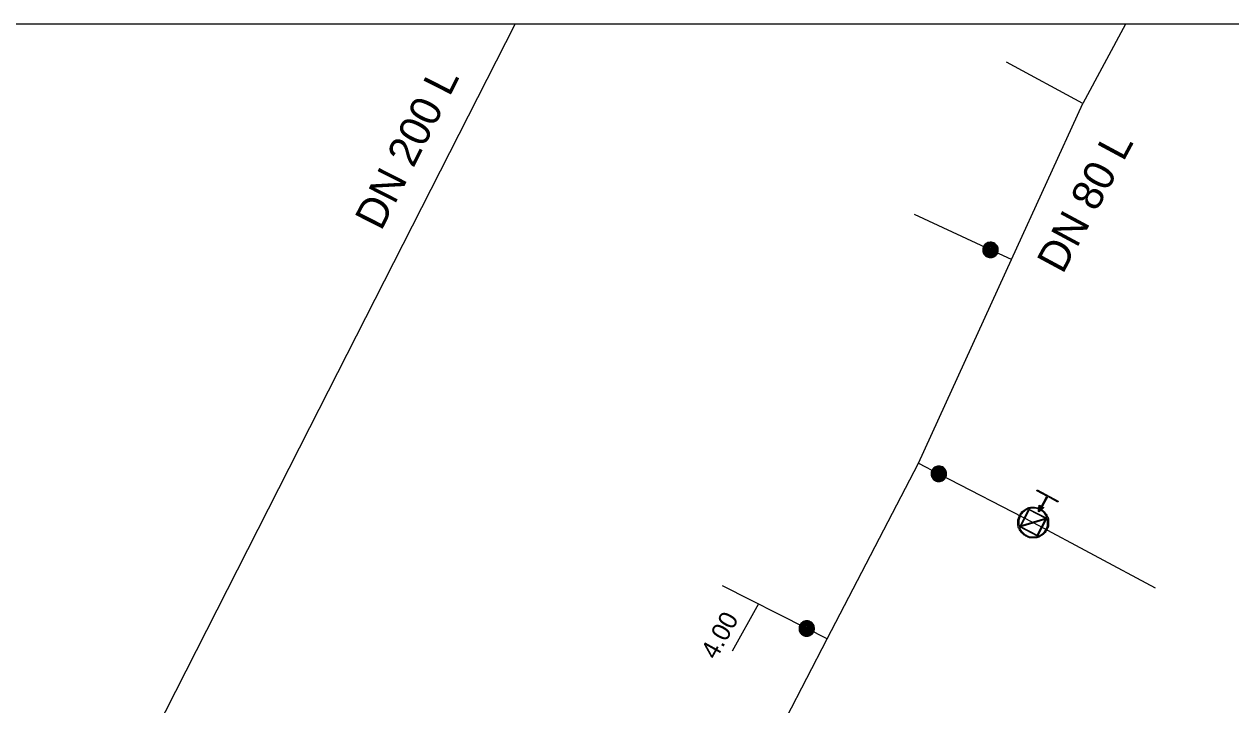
# Model space of a CAD drawing. Extents: x -820257 to -819974, y -1070894 to -1070484.
# Drawn here: x -820109.2 to -820030.6, y -1070528.7 to -1070484.4 of the extents above; entities that cross this region are included whole.
import ezdxf

# ---------------------------------------------------------------- set-up
doc = ezdxf.new("R2010")
doc.units = 0
for name, color, linetype in [('Default', 7, 'Continuous'), ('Hydrant', 7, 'Continuous'), ('Oměrka vodovodu', 7, 'Continuous'), ('Oměrka-text', 7, 'Continuous'), ('Přípojka vodovodu', 7, 'Continuous'), ('Přípojkový uzávěr', 7, 'Continuous'), ('Roz-řad', 7, 'Continuous'), ('Roz-řad-popis základní', 7, 'Continuous'), ('Šachta vodovodní', 7, 'Continuous')]:
    doc.layers.add(name, color=color, linetype=linetype)

msp = doc.modelspace()

# ---------------------------------------------------------------- linework, layer by layer
at = {"layer": 'Default'}
msp.add_lwpolyline([(-819975.603, -1070484.403), (-820256.81, -1070484.403), (-820256.81, -1070893.932)], dxfattribs=at)
at = {"layer": 'Hydrant'}
for points in [[(-820043.051, -1070515.965), (-820042.608, -1070515.138), (-820043.27, -1070514.785), (-820043.24, -1070514.73), (-820041.862, -1070515.466), (-820041.892, -1070515.522), (-820042.553, -1070515.168), (-820042.995, -1070515.995)], [(-820044.402, -1070517.105), (-820042.605, -1070516.56)], [(-820042.587, -1070516.618), (-820044.385, -1070517.165)]]:
    msp.add_lwpolyline(points, dxfattribs=at)
for points in [[(-820042.995, -1070515.995), (-820042.791, -1070516.113), (-820042.65, -1070516.326), (-820042.5, -1070516.552), (-820042.495, -1070516.827), (-820042.489, -1070517.102), (-820042.613, -1070517.333), (-820042.735, -1070517.562), (-820042.964, -1070517.71), (-820043.192, -1070517.858), (-820043.465, -1070517.862), (-820043.737, -1070517.866), (-820043.966, -1070517.744), (-820044.195, -1070517.621), (-820044.343, -1070517.392), (-820044.491, -1070517.164), (-820044.495, -1070516.892), (-820044.499, -1070516.619), (-820044.376, -1070516.39), (-820044.253, -1070516.159), (-820044.021, -1070516.011), (-820043.789, -1070515.863), (-820043.518, -1070515.861), (-820043.264, -1070515.86), (-820043.051, -1070515.965)], [(-820042.605, -1070516.56), (-820042.641, -1070516.454), (-820042.703, -1070516.359), (-820042.844, -1070516.146), (-820043.052, -1070516.035), (-820043.261, -1070515.924), (-820043.516, -1070515.924), (-820043.771, -1070515.925), (-820043.988, -1070516.064), (-820044.205, -1070516.203), (-820044.321, -1070516.42), (-820044.436, -1070516.635), (-820044.431, -1070516.89), (-820044.431, -1070517.001), (-820044.402, -1070517.105)], [(-820044.385, -1070517.165), (-820044.351, -1070517.266), (-820044.289, -1070517.358), (-820044.152, -1070517.573), (-820043.937, -1070517.688), (-820043.721, -1070517.804), (-820043.466, -1070517.8), (-820043.21, -1070517.796), (-820042.996, -1070517.657), (-820042.783, -1070517.519), (-820042.668, -1070517.304), (-820042.552, -1070517.087), (-820042.558, -1070516.829), (-820042.561, -1070516.719), (-820042.587, -1070516.618)]]:
    msp.add_open_spline(points, degree=3, dxfattribs=at)
at = {"layer": 'Oměrka vodovodu'}
msp.add_line((-820061.389, -1070522.16), (-820063.095, -1070525.238), dxfattribs=at)
at = {"layer": 'Přípojka vodovodu'}
for p, q in [((-820040.271, -1070489.57), (-820045.234, -1070486.875)), ((-820043.495, -1070516.863), (-820035.556, -1070521.108))]:
    msp.add_line(p, q, dxfattribs=at)
for points in [[(-820044.916, -1070499.74), (-820046.276, -1070499.108), (-820051.225, -1070496.806)], [(-820050.972, -1070512.997), (-820049.64, -1070513.686), (-820043.495, -1070516.863)], [(-820056.904, -1070524.441), (-820058.241, -1070523.761), (-820063.715, -1070520.977)]]:
    msp.add_lwpolyline(points, dxfattribs=at)
at = {"layer": 'Přípojkový uzávěr'}
for points in [[(-820046.065, -1070498.654), (-820045.951, -1070498.707), (-820045.87, -1070498.816), (-820045.789, -1070498.925), (-820045.778, -1070499.062), (-820045.767, -1070499.2), (-820045.823, -1070499.319), (-820045.877, -1070499.437), (-820045.987, -1070499.517), (-820046.097, -1070499.597), (-820046.233, -1070499.606), (-820046.369, -1070499.616), (-820046.487, -1070499.561), (-820046.604, -1070499.506), (-820046.685, -1070499.396), (-820046.765, -1070499.286), (-820046.775, -1070499.15), (-820046.784, -1070499.015), (-820046.729, -1070498.897), (-820046.674, -1070498.778), (-820046.563, -1070498.698), (-820046.451, -1070498.617), (-820046.315, -1070498.609), (-820046.18, -1070498.601), (-820046.065, -1070498.654)], [(-820046.085, -1070498.696), (-820046.189, -1070498.648), (-820046.312, -1070498.655), (-820046.435, -1070498.663), (-820046.536, -1070498.736), (-820046.637, -1070498.809), (-820046.687, -1070498.917), (-820046.736, -1070499.024), (-820046.728, -1070499.146), (-820046.719, -1070499.269), (-820046.646, -1070499.369), (-820046.574, -1070499.469), (-820046.467, -1070499.518), (-820046.36, -1070499.568), (-820046.237, -1070499.559), (-820046.114, -1070499.551), (-820046.014, -1070499.478), (-820045.915, -1070499.406), (-820045.865, -1070499.299), (-820045.815, -1070499.191), (-820045.825, -1070499.067), (-820045.835, -1070498.942), (-820045.908, -1070498.843), (-820045.982, -1070498.745), (-820046.085, -1070498.696)], [(-820046.1, -1070498.727), (-820046.003, -1070498.772), (-820045.936, -1070498.863), (-820045.868, -1070498.954), (-820045.859, -1070499.07), (-820045.85, -1070499.185), (-820045.896, -1070499.285), (-820045.942, -1070499.383), (-820046.034, -1070499.45), (-820046.126, -1070499.518), (-820046.24, -1070499.525), (-820046.354, -1070499.533), (-820046.453, -1070499.487), (-820046.551, -1070499.441), (-820046.619, -1070499.349), (-820046.686, -1070499.257), (-820046.694, -1070499.143), (-820046.702, -1070499.03), (-820046.656, -1070498.931), (-820046.61, -1070498.832), (-820046.516, -1070498.764), (-820046.423, -1070498.696), (-820046.309, -1070498.69), (-820046.195, -1070498.683), (-820046.1, -1070498.727)], [(-820046.119, -1070498.767), (-820046.26, -1070498.701), (-820046.405, -1070498.755), (-820046.55, -1070498.809), (-820046.616, -1070498.95), (-820046.682, -1070499.091), (-820046.628, -1070499.236), (-820046.575, -1070499.382), (-820046.435, -1070499.447), (-820046.293, -1070499.513), (-820046.147, -1070499.46), (-820046.001, -1070499.407), (-820045.936, -1070499.266), (-820045.87, -1070499.125), (-820045.923, -1070498.979), (-820045.976, -1070498.834), (-820046.119, -1070498.767)], [(-820046.138, -1070498.809), (-820046.013, -1070498.867), (-820045.967, -1070498.994), (-820045.921, -1070499.121), (-820045.979, -1070499.245), (-820046.036, -1070499.368), (-820046.164, -1070499.415), (-820046.291, -1070499.461), (-820046.415, -1070499.404), (-820046.539, -1070499.346), (-820046.585, -1070499.219), (-820046.631, -1070499.091), (-820046.574, -1070498.968), (-820046.516, -1070498.844), (-820046.389, -1070498.798), (-820046.262, -1070498.751), (-820046.138, -1070498.809)], [(-820046.155, -1070498.845), (-820046.263, -1070498.794), (-820046.375, -1070498.835), (-820046.487, -1070498.876), (-820046.538, -1070498.984), (-820046.588, -1070499.093), (-820046.548, -1070499.205), (-820046.507, -1070499.317), (-820046.398, -1070499.368), (-820046.289, -1070499.418), (-820046.177, -1070499.377), (-820046.065, -1070499.336), (-820046.015, -1070499.228), (-820045.964, -1070499.119), (-820046.005, -1070499.007), (-820046.045, -1070498.895), (-820046.155, -1070498.845)], [(-820046.171, -1070498.881), (-820046.076, -1070498.925), (-820046.041, -1070499.022), (-820046.005, -1070499.119), (-820046.049, -1070499.213), (-820046.093, -1070499.307), (-820046.19, -1070499.343), (-820046.287, -1070499.378), (-820046.382, -1070499.334), (-820046.475, -1070499.291), (-820046.511, -1070499.193), (-820046.546, -1070499.096), (-820046.503, -1070499.002), (-820046.459, -1070498.908), (-820046.362, -1070498.872), (-820046.266, -1070498.837), (-820046.171, -1070498.881)], [(-820046.19, -1070498.923), (-820046.267, -1070498.887), (-820046.346, -1070498.916), (-820046.425, -1070498.945), (-820046.46, -1070499.021), (-820046.496, -1070499.098), (-820046.467, -1070499.177), (-820046.438, -1070499.255), (-820046.362, -1070499.291), (-820046.286, -1070499.326), (-820046.206, -1070499.298), (-820046.127, -1070499.269), (-820046.092, -1070499.192), (-820046.056, -1070499.116), (-820046.085, -1070499.037), (-820046.114, -1070498.958), (-820046.19, -1070498.923)], [(-820046.205, -1070498.954), (-820046.141, -1070498.984), (-820046.117, -1070499.049), (-820046.094, -1070499.114), (-820046.123, -1070499.178), (-820046.153, -1070499.242), (-820046.218, -1070499.265), (-820046.284, -1070499.289), (-820046.347, -1070499.26), (-820046.411, -1070499.23), (-820046.435, -1070499.165), (-820046.458, -1070499.1), (-820046.429, -1070499.036), (-820046.399, -1070498.972), (-820046.334, -1070498.948), (-820046.269, -1070498.924), (-820046.205, -1070498.954)], [(-820046.224, -1070498.994), (-820046.27, -1070498.972), (-820046.319, -1070498.99), (-820046.367, -1070499.008), (-820046.389, -1070499.055), (-820046.411, -1070499.102), (-820046.393, -1070499.15), (-820046.375, -1070499.199), (-820046.329, -1070499.221), (-820046.282, -1070499.243), (-820046.233, -1070499.225), (-820046.184, -1070499.207), (-820046.162, -1070499.16), (-820046.141, -1070499.113), (-820046.158, -1070499.065), (-820046.176, -1070499.016), (-820046.224, -1070498.994)], [(-820046.243, -1070499.036), (-820046.213, -1070499.05), (-820046.202, -1070499.08), (-820046.191, -1070499.11), (-820046.205, -1070499.14), (-820046.219, -1070499.169), (-820046.249, -1070499.181), (-820046.279, -1070499.192), (-820046.309, -1070499.178), (-820046.338, -1070499.165), (-820046.35, -1070499.134), (-820046.361, -1070499.104), (-820046.347, -1070499.074), (-820046.333, -1070499.044), (-820046.303, -1070499.034), (-820046.273, -1070499.023), (-820046.243, -1070499.036)], [(-820046.256, -1070499.065), (-820046.274, -1070499.057), (-820046.292, -1070499.063), (-820046.31, -1070499.069), (-820046.319, -1070499.087), (-820046.327, -1070499.105), (-820046.32, -1070499.123), (-820046.314, -1070499.142), (-820046.296, -1070499.15), (-820046.278, -1070499.158), (-820046.26, -1070499.151), (-820046.242, -1070499.145), (-820046.234, -1070499.127), (-820046.225, -1070499.109), (-820046.232, -1070499.091), (-820046.238, -1070499.073), (-820046.256, -1070499.065)], [(-820049.411, -1070513.241), (-820049.299, -1070513.299), (-820049.222, -1070513.411), (-820049.146, -1070513.523), (-820049.141, -1070513.661), (-820049.136, -1070513.799), (-820049.196, -1070513.916), (-820049.256, -1070514.031), (-820049.369, -1070514.106), (-820049.482, -1070514.182), (-820049.618, -1070514.185), (-820049.754, -1070514.189), (-820049.87, -1070514.129), (-820049.985, -1070514.07), (-820050.061, -1070513.957), (-820050.136, -1070513.843), (-820050.14, -1070513.708), (-820050.144, -1070513.572), (-820050.085, -1070513.456), (-820050.024, -1070513.34), (-820049.91, -1070513.264), (-820049.795, -1070513.188), (-820049.659, -1070513.185), (-820049.523, -1070513.183), (-820049.411, -1070513.241)], [(-820049.433, -1070513.283), (-820049.534, -1070513.23), (-820049.657, -1070513.232), (-820049.78, -1070513.234), (-820049.884, -1070513.303), (-820049.988, -1070513.372), (-820050.043, -1070513.478), (-820050.097, -1070513.582), (-820050.094, -1070513.705), (-820050.09, -1070513.828), (-820050.021, -1070513.931), (-820049.953, -1070514.034), (-820049.849, -1070514.088), (-820049.744, -1070514.142), (-820049.62, -1070514.139), (-820049.497, -1070514.135), (-820049.394, -1070514.067), (-820049.292, -1070513.999), (-820049.238, -1070513.894), (-820049.183, -1070513.789), (-820049.188, -1070513.663), (-820049.192, -1070513.538), (-820049.262, -1070513.437), (-820049.331, -1070513.335), (-820049.433, -1070513.283)], [(-820049.448, -1070513.313), (-820049.354, -1070513.362), (-820049.29, -1070513.456), (-820049.226, -1070513.549), (-820049.222, -1070513.665), (-820049.218, -1070513.781), (-820049.268, -1070513.878), (-820049.318, -1070513.975), (-820049.413, -1070514.038), (-820049.507, -1070514.102), (-820049.622, -1070514.105), (-820049.736, -1070514.108), (-820049.833, -1070514.057), (-820049.929, -1070514.008), (-820049.993, -1070513.913), (-820050.057, -1070513.818), (-820050.06, -1070513.704), (-820050.063, -1070513.59), (-820050.013, -1070513.494), (-820049.962, -1070513.396), (-820049.866, -1070513.332), (-820049.77, -1070513.268), (-820049.656, -1070513.267), (-820049.542, -1070513.265), (-820049.448, -1070513.313)], [(-820049.469, -1070513.352), (-820049.608, -1070513.28), (-820049.755, -1070513.328), (-820049.902, -1070513.375), (-820049.974, -1070513.514), (-820050.045, -1070513.652), (-820049.998, -1070513.799), (-820049.95, -1070513.947), (-820049.813, -1070514.018), (-820049.675, -1070514.09), (-820049.527, -1070514.043), (-820049.379, -1070513.996), (-820049.307, -1070513.858), (-820049.236, -1070513.72), (-820049.282, -1070513.572), (-820049.329, -1070513.424), (-820049.469, -1070513.352)], [(-820049.49, -1070513.393), (-820049.368, -1070513.456), (-820049.327, -1070513.585), (-820049.287, -1070513.714), (-820049.349, -1070513.835), (-820049.412, -1070513.956), (-820049.541, -1070513.997), (-820049.67, -1070514.038), (-820049.791, -1070513.976), (-820049.913, -1070513.913), (-820049.954, -1070513.784), (-820049.995, -1070513.654), (-820049.932, -1070513.533), (-820049.87, -1070513.412), (-820049.74, -1070513.371), (-820049.611, -1070513.33), (-820049.49, -1070513.393)], [(-820049.508, -1070513.428), (-820049.615, -1070513.373), (-820049.728, -1070513.409), (-820049.842, -1070513.445), (-820049.897, -1070513.552), (-820049.952, -1070513.658), (-820049.916, -1070513.772), (-820049.88, -1070513.885), (-820049.773, -1070513.941), (-820049.667, -1070513.995), (-820049.553, -1070513.959), (-820049.439, -1070513.923), (-820049.384, -1070513.817), (-820049.329, -1070513.71), (-820049.365, -1070513.597), (-820049.401, -1070513.483), (-820049.508, -1070513.428)], [(-820049.526, -1070513.463), (-820049.433, -1070513.511), (-820049.402, -1070513.61), (-820049.371, -1070513.708), (-820049.418, -1070513.801), (-820049.466, -1070513.893), (-820049.564, -1070513.924), (-820049.663, -1070513.955), (-820049.755, -1070513.907), (-820049.847, -1070513.86), (-820049.879, -1070513.762), (-820049.91, -1070513.663), (-820049.863, -1070513.571), (-820049.815, -1070513.479), (-820049.717, -1070513.447), (-820049.619, -1070513.415), (-820049.526, -1070513.463)], [(-820049.547, -1070513.504), (-820049.622, -1070513.466), (-820049.702, -1070513.491), (-820049.782, -1070513.517), (-820049.821, -1070513.592), (-820049.86, -1070513.667), (-820049.834, -1070513.747), (-820049.809, -1070513.826), (-820049.734, -1070513.865), (-820049.659, -1070513.904), (-820049.579, -1070513.879), (-820049.499, -1070513.853), (-820049.46, -1070513.778), (-820049.421, -1070513.703), (-820049.447, -1070513.623), (-820049.472, -1070513.543), (-820049.547, -1070513.504)], [(-820049.563, -1070513.535), (-820049.501, -1070513.568), (-820049.48, -1070513.634), (-820049.458, -1070513.7), (-820049.491, -1070513.762), (-820049.523, -1070513.825), (-820049.589, -1070513.846), (-820049.656, -1070513.867), (-820049.718, -1070513.834), (-820049.78, -1070513.802), (-820049.801, -1070513.736), (-820049.822, -1070513.67), (-820049.79, -1070513.607), (-820049.758, -1070513.545), (-820049.692, -1070513.524), (-820049.626, -1070513.503), (-820049.563, -1070513.535)], [(-820049.583, -1070513.574), (-820049.629, -1070513.55), (-820049.678, -1070513.566), (-820049.727, -1070513.582), (-820049.751, -1070513.628), (-820049.775, -1070513.674), (-820049.759, -1070513.723), (-820049.744, -1070513.773), (-820049.698, -1070513.796), (-820049.652, -1070513.82), (-820049.602, -1070513.805), (-820049.553, -1070513.789), (-820049.529, -1070513.743), (-820049.505, -1070513.697), (-820049.521, -1070513.648), (-820049.536, -1070513.598), (-820049.583, -1070513.574)], [(-820049.605, -1070513.616), (-820049.575, -1070513.631), (-820049.566, -1070513.661), (-820049.556, -1070513.692), (-820049.571, -1070513.721), (-820049.586, -1070513.75), (-820049.617, -1070513.76), (-820049.647, -1070513.77), (-820049.677, -1070513.755), (-820049.705, -1070513.74), (-820049.715, -1070513.709), (-820049.725, -1070513.678), (-820049.71, -1070513.649), (-820049.695, -1070513.62), (-820049.664, -1070513.61), (-820049.633, -1070513.601), (-820049.605, -1070513.616)], [(-820049.619, -1070513.644), (-820049.636, -1070513.635), (-820049.655, -1070513.64), (-820049.673, -1070513.646), (-820049.682, -1070513.664), (-820049.691, -1070513.681), (-820049.685, -1070513.7), (-820049.68, -1070513.718), (-820049.662, -1070513.727), (-820049.644, -1070513.736), (-820049.626, -1070513.73), (-820049.608, -1070513.724), (-820049.599, -1070513.707), (-820049.59, -1070513.689), (-820049.596, -1070513.671), (-820049.601, -1070513.653), (-820049.619, -1070513.644)], [(-820058.014, -1070523.315), (-820057.902, -1070523.372), (-820057.825, -1070523.484), (-820057.747, -1070523.596), (-820057.742, -1070523.734), (-820057.736, -1070523.871), (-820057.795, -1070523.988), (-820057.854, -1070524.104), (-820057.967, -1070524.18), (-820058.079, -1070524.256), (-820058.215, -1070524.261), (-820058.352, -1070524.266), (-820058.468, -1070524.206), (-820058.583, -1070524.148), (-820058.659, -1070524.035), (-820058.736, -1070523.922), (-820058.741, -1070523.786), (-820058.745, -1070523.651), (-820058.687, -1070523.535), (-820058.627, -1070523.418), (-820058.513, -1070523.341), (-820058.398, -1070523.264), (-820058.263, -1070523.261), (-820058.127, -1070523.258), (-820058.014, -1070523.315)], [(-820058.036, -1070523.357), (-820058.138, -1070523.305), (-820058.261, -1070523.308), (-820058.384, -1070523.311), (-820058.487, -1070523.381), (-820058.591, -1070523.45), (-820058.645, -1070523.556), (-820058.698, -1070523.661), (-820058.694, -1070523.784), (-820058.69, -1070523.907), (-820058.62, -1070524.009), (-820058.551, -1070524.112), (-820058.447, -1070524.165), (-820058.341, -1070524.218), (-820058.218, -1070524.214), (-820058.094, -1070524.21), (-820057.992, -1070524.141), (-820057.89, -1070524.072), (-820057.837, -1070523.967), (-820057.783, -1070523.861), (-820057.789, -1070523.736), (-820057.794, -1070523.611), (-820057.864, -1070523.51), (-820057.934, -1070523.409), (-820058.036, -1070523.357)], [(-820058.051, -1070523.387), (-820057.957, -1070523.435), (-820057.892, -1070523.529), (-820057.828, -1070523.622), (-820057.823, -1070523.738), (-820057.818, -1070523.853), (-820057.867, -1070523.951), (-820057.917, -1070524.048), (-820058.011, -1070524.112), (-820058.105, -1070524.176), (-820058.219, -1070524.18), (-820058.334, -1070524.184), (-820058.431, -1070524.134), (-820058.528, -1070524.085), (-820058.592, -1070523.99), (-820058.656, -1070523.896), (-820058.66, -1070523.782), (-820058.664, -1070523.669), (-820058.614, -1070523.572), (-820058.565, -1070523.474), (-820058.469, -1070523.409), (-820058.373, -1070523.345), (-820058.259, -1070523.342), (-820058.145, -1070523.34), (-820058.051, -1070523.387)], [(-820058.072, -1070523.426), (-820058.211, -1070523.355), (-820058.358, -1070523.404), (-820058.505, -1070523.453), (-820058.575, -1070523.591), (-820058.646, -1070523.73), (-820058.597, -1070523.877), (-820058.549, -1070524.025), (-820058.412, -1070524.095), (-820058.272, -1070524.166), (-820058.125, -1070524.118), (-820057.977, -1070524.07), (-820057.907, -1070523.931), (-820057.836, -1070523.793), (-820057.883, -1070523.645), (-820057.931, -1070523.498), (-820058.072, -1070523.426)], [(-820058.092, -1070523.467), (-820057.97, -1070523.529), (-820057.928, -1070523.658), (-820057.887, -1070523.787), (-820057.949, -1070523.908), (-820058.01, -1070524.03), (-820058.139, -1070524.072), (-820058.268, -1070524.114), (-820058.39, -1070524.052), (-820058.512, -1070523.99), (-820058.554, -1070523.861), (-820058.595, -1070523.732), (-820058.534, -1070523.611), (-820058.472, -1070523.49), (-820058.343, -1070523.447), (-820058.214, -1070523.405), (-820058.092, -1070523.467)], [(-820058.11, -1070523.502), (-820058.217, -1070523.448), (-820058.331, -1070523.485), (-820058.444, -1070523.522), (-820058.498, -1070523.629), (-820058.553, -1070523.735), (-820058.516, -1070523.849), (-820058.479, -1070523.962), (-820058.372, -1070524.017), (-820058.265, -1070524.071), (-820058.152, -1070524.034), (-820058.038, -1070523.997), (-820057.984, -1070523.89), (-820057.93, -1070523.784), (-820057.966, -1070523.671), (-820058.003, -1070523.557), (-820058.11, -1070523.502)], [(-820058.128, -1070523.538), (-820058.034, -1070523.586), (-820058.003, -1070523.684), (-820057.971, -1070523.782), (-820058.018, -1070523.875), (-820058.065, -1070523.967), (-820058.163, -1070523.999), (-820058.262, -1070524.031), (-820058.354, -1070523.984), (-820058.446, -1070523.937), (-820058.478, -1070523.839), (-820058.511, -1070523.74), (-820058.464, -1070523.648), (-820058.417, -1070523.555), (-820058.319, -1070523.523), (-820058.221, -1070523.491), (-820058.128, -1070523.538)], [(-820058.149, -1070523.579), (-820058.224, -1070523.541), (-820058.304, -1070523.567), (-820058.384, -1070523.593), (-820058.422, -1070523.668), (-820058.46, -1070523.744), (-820058.434, -1070523.823), (-820058.408, -1070523.903), (-820058.333, -1070523.941), (-820058.258, -1070523.979), (-820058.178, -1070523.954), (-820058.098, -1070523.928), (-820058.06, -1070523.852), (-820058.022, -1070523.777), (-820058.048, -1070523.697), (-820058.074, -1070523.618), (-820058.149, -1070523.579)], [(-820058.165, -1070523.61), (-820058.102, -1070523.642), (-820058.08, -1070523.708), (-820058.059, -1070523.774), (-820058.091, -1070523.837), (-820058.123, -1070523.899), (-820058.189, -1070523.921), (-820058.255, -1070523.942), (-820058.317, -1070523.91), (-820058.38, -1070523.879), (-820058.401, -1070523.813), (-820058.423, -1070523.747), (-820058.391, -1070523.684), (-820058.359, -1070523.621), (-820058.293, -1070523.6), (-820058.227, -1070523.578), (-820058.165, -1070523.61)], [(-820058.184, -1070523.649), (-820058.231, -1070523.626), (-820058.28, -1070523.642), (-820058.329, -1070523.658), (-820058.352, -1070523.704), (-820058.376, -1070523.75), (-820058.36, -1070523.8), (-820058.343, -1070523.849), (-820058.298, -1070523.872), (-820058.251, -1070523.896), (-820058.202, -1070523.88), (-820058.153, -1070523.864), (-820058.129, -1070523.818), (-820058.106, -1070523.772), (-820058.122, -1070523.722), (-820058.137, -1070523.673), (-820058.184, -1070523.649)], [(-820058.206, -1070523.691), (-820058.176, -1070523.706), (-820058.166, -1070523.736), (-820058.156, -1070523.767), (-820058.171, -1070523.796), (-820058.186, -1070523.825), (-820058.216, -1070523.835), (-820058.247, -1070523.845), (-820058.277, -1070523.83), (-820058.305, -1070523.816), (-820058.315, -1070523.785), (-820058.325, -1070523.754), (-820058.311, -1070523.725), (-820058.296, -1070523.696), (-820058.265, -1070523.686), (-820058.234, -1070523.677), (-820058.206, -1070523.691)], [(-820058.22, -1070523.719), (-820058.237, -1070523.71), (-820058.256, -1070523.716), (-820058.274, -1070523.722), (-820058.283, -1070523.74), (-820058.292, -1070523.757), (-820058.286, -1070523.775), (-820058.28, -1070523.794), (-820058.262, -1070523.803), (-820058.245, -1070523.812), (-820058.226, -1070523.806), (-820058.208, -1070523.799), (-820058.199, -1070523.782), (-820058.19, -1070523.764), (-820058.196, -1070523.746), (-820058.202, -1070523.728), (-820058.22, -1070523.719)]]:
    msp.add_open_spline(points, degree=3, dxfattribs=at)
at = {"layer": 'Roz-řad'}
for p, q in [((-820090.584, -1070510.68), (-820077.219, -1070484.403)), ((-820111.356, -1070551.519), (-820090.584, -1070510.68))]:
    msp.add_line(p, q, dxfattribs=at)
for points in [[(-820037.489, -1070484.403), (-820040.271, -1070489.57)], [(-820050.972, -1070512.997), (-820044.916, -1070499.74), (-820040.271, -1070489.57)], [(-820073.442, -1070556.519), (-820070.878, -1070551.68), (-820065.83, -1070541.39), (-820062.208, -1070534.681), (-820056.904, -1070524.441), (-820050.972, -1070512.997)]]:
    msp.add_lwpolyline(points, dxfattribs=at)
at = {"layer": 'Šachta vodovodní'}
for points in [[(-820043.145, -1070516.13), (-820043.102, -1070515.732), (-820043.054, -1070515.756), (-820043.092, -1070516.041)], [(-820042.619, -1070516.584), (-820043.216, -1070517.739), (-820044.371, -1070517.142), (-820043.774, -1070515.987), (-820042.619, -1070516.584)], [(-820043.757, -1070516.042), (-820044.316, -1070517.125), (-820043.234, -1070517.684), (-820042.674, -1070516.602), (-820043.757, -1070516.042)], [(-820043.057, -1070516.06), (-820042.844, -1070515.865), (-820042.798, -1070515.889), (-820043.1, -1070516.153), (-820043.145, -1070516.13)]]:
    msp.add_lwpolyline(points, dxfattribs=at)
msp.add_open_spline([(-820043.092, -1070516.041), (-820043.097, -1070516.076), (-820043.103, -1070516.104), (-820043.081, -1070516.081), (-820043.057, -1070516.06)], degree=3, dxfattribs=at)

# ---------------------------------------------------------------- texts
at = {"layer": 'Oměrka-text'}
msp.add_text(' 4.00', height=1.2, rotation=61.0023, dxfattribs=at).set_placement((-820064.367, -1070526.234))
at = {"layer": 'Roz-řad-popis základní'}
for s, rotation, p in [('DN 200 L', 63.0418, (-820085.947, -1070497.925)), ('DN 80 L', 61.69873, (-820041.58, -1070500.736))]:
    msp.add_text(s, height=2, rotation=rotation, dxfattribs=at).set_placement(p)

doc.saveas('drawing.dxf')
